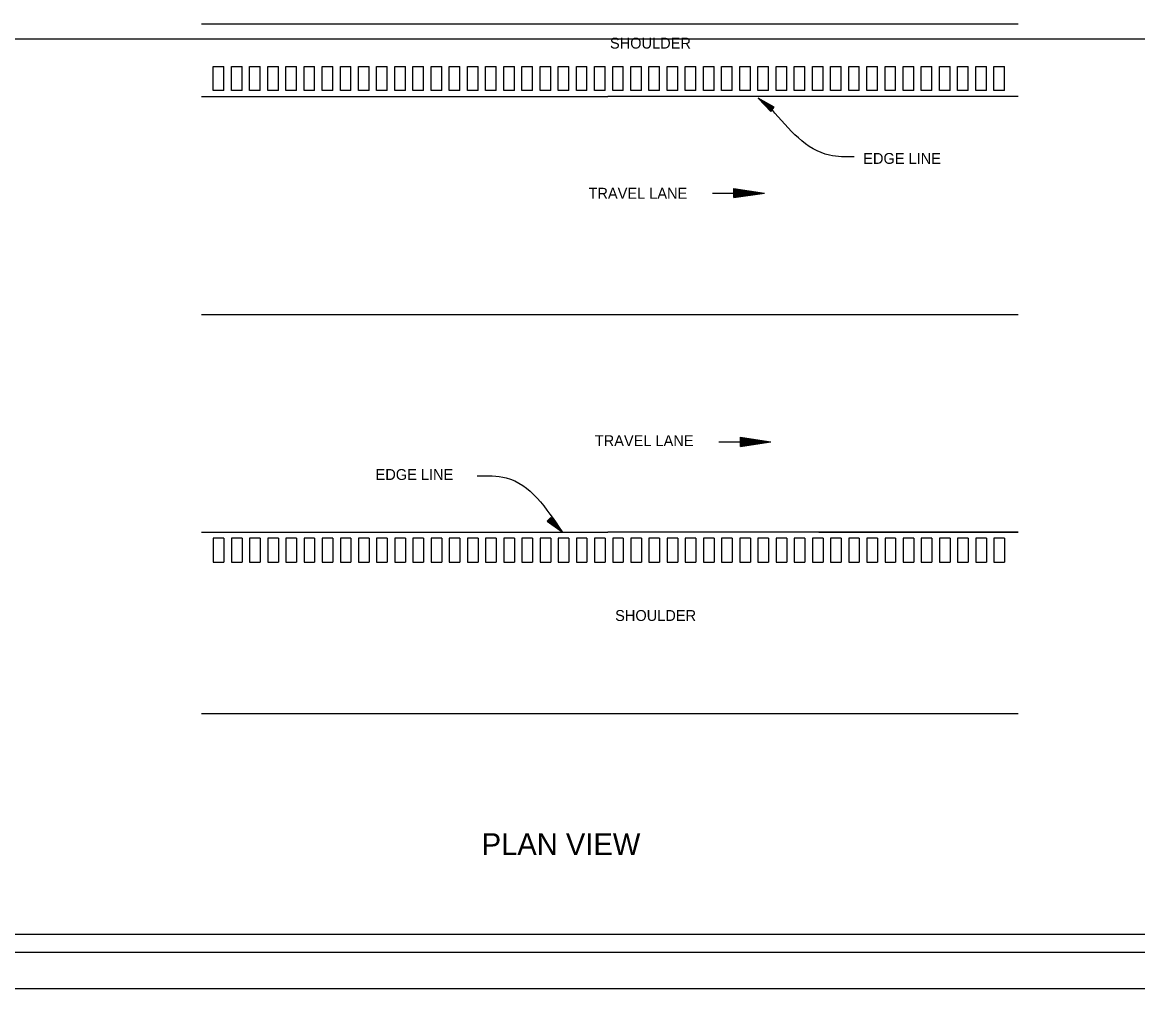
# Model space of a CAD drawing. Extents: x 1372039 to 1372773, y 376713 to 376926.
# Drawn here: x 1372550.8 to 1372673.7, y 376712.7 to 376819.2 of the extents above; entities that cross this region are included whole.
import ezdxf

# ---------------------------------------------------------------- set-up
doc = ezdxf.new("R2010")
doc.units = 0
for name, color, linetype in [('R_Border', 7, 'Continuous'), ('R_Draft', 7, 'Continuous'), ('R_No Plot', 7, 'Continuous')]:
    doc.layers.add(name, color=color, linetype=linetype)

msp = doc.modelspace()

# ---------------------------------------------------------------- linework, layer by layer
at = {"layer": 'R_Border'}
msp.add_line((1372768.01, 376716.65), (1372451.83, 376716.65), dxfattribs=at)
at = {"layer": 'R_Draft'}
for p, q in [((1372570.54, 376819), (1372660.51, 376819)), ((1372571.84, 376811.66), (1372571.84, 376814.32)), ((1372571.84, 376814.32), (1372573.01, 376814.32)), ((1372573.01, 376811.66), (1372573.01, 376814.32)), ((1372573.84, 376811.66), (1372573.84, 376814.32)), ((1372573.84, 376814.32), (1372575.01, 376814.32)), ((1372575.01, 376811.66), (1372575.01, 376814.32)), ((1372575.84, 376811.66), (1372575.84, 376814.32)), ((1372575.84, 376814.32), (1372577.01, 376814.32)), ((1372577.01, 376811.66), (1372577.01, 376814.32)), ((1372577.84, 376811.66), (1372577.84, 376814.32)), ((1372577.84, 376814.32), (1372579.01, 376814.32)), ((1372579.01, 376811.66), (1372579.01, 376814.32)), ((1372579.84, 376811.66), (1372579.84, 376814.32)), ((1372579.84, 376814.32), (1372581.01, 376814.32)), ((1372581.01, 376811.66), (1372581.01, 376814.32)), ((1372581.84, 376811.66), (1372581.84, 376814.32)), ((1372581.84, 376814.32), (1372583.01, 376814.32)), ((1372583.01, 376811.66), (1372583.01, 376814.32)), ((1372583.84, 376811.66), (1372583.84, 376814.32)), ((1372583.84, 376814.32), (1372585.01, 376814.32)), ((1372585.01, 376811.66), (1372585.01, 376814.32)), ((1372585.84, 376811.66), (1372585.84, 376814.32)), ((1372585.84, 376814.32), (1372587.01, 376814.32)), ((1372587.01, 376811.66), (1372587.01, 376814.32)), ((1372587.84, 376811.66), (1372587.84, 376814.32)), ((1372587.84, 376814.32), (1372589.01, 376814.32)), ((1372589.01, 376811.66), (1372589.01, 376814.32)), ((1372589.84, 376811.66), (1372589.84, 376814.32)), ((1372589.84, 376814.32), (1372591.01, 376814.32)), ((1372591.01, 376811.66), (1372591.01, 376814.32)), ((1372591.84, 376811.66), (1372591.84, 376814.32)), ((1372591.84, 376814.32), (1372593.01, 376814.32)), ((1372593.01, 376811.66), (1372593.01, 376814.32)), ((1372593.84, 376811.66), (1372593.84, 376814.32)), ((1372593.84, 376814.32), (1372595.01, 376814.32)), ((1372595.01, 376811.66), (1372595.01, 376814.32)), ((1372595.84, 376811.66), (1372595.84, 376814.32)), ((1372595.84, 376814.32), (1372597.01, 376814.32)), ((1372597.01, 376811.66), (1372597.01, 376814.32)), ((1372597.84, 376811.66), (1372597.84, 376814.32)), ((1372597.84, 376814.32), (1372599.01, 376814.32)), ((1372599.01, 376811.66), (1372599.01, 376814.32)), ((1372599.84, 376811.66), (1372599.84, 376814.32)), ((1372599.84, 376814.32), (1372601.01, 376814.32)), ((1372601.01, 376811.66), (1372601.01, 376814.32)), ((1372601.84, 376811.66), (1372601.84, 376814.32)), ((1372601.84, 376811.66), (1372601.84, 376814.32)), ((1372601.84, 376814.32), (1372603.01, 376814.32)), ((1372603.01, 376811.66), (1372603.01, 376814.32)), ((1372603.84, 376811.66), (1372603.84, 376814.32)), ((1372603.84, 376814.32), (1372605.01, 376814.32)), ((1372605.01, 376811.66), (1372605.01, 376814.32)), ((1372605.84, 376811.66), (1372605.84, 376814.32)), ((1372605.84, 376814.32), (1372607.01, 376814.32)), ((1372607.01, 376811.66), (1372607.01, 376814.32)), ((1372607.84, 376811.66), (1372607.84, 376814.32)), ((1372607.84, 376814.32), (1372609.01, 376814.32)), ((1372609.01, 376811.66), (1372609.01, 376814.32)), ((1372609.84, 376811.66), (1372609.84, 376814.32)), ((1372609.84, 376814.32), (1372611.01, 376814.32)), ((1372611.01, 376811.66), (1372611.01, 376814.32)), ((1372611.84, 376811.66), (1372611.84, 376814.32)), ((1372611.84, 376814.32), (1372613.01, 376814.32)), ((1372613.01, 376811.66), (1372613.01, 376814.32)), ((1372613.84, 376811.66), (1372613.84, 376814.32)), ((1372613.84, 376814.32), (1372615.01, 376814.32)), ((1372615.01, 376811.66), (1372615.01, 376814.32)), ((1372615.84, 376811.66), (1372615.84, 376814.32)), ((1372615.84, 376814.32), (1372617.01, 376814.32)), ((1372617.01, 376811.66), (1372617.01, 376814.32)), ((1372617.84, 376811.66), (1372617.84, 376814.32)), ((1372617.84, 376814.32), (1372619.01, 376814.32)), ((1372619.01, 376811.66), (1372619.01, 376814.32)), ((1372619.84, 376811.66), (1372619.84, 376814.32)), ((1372619.84, 376814.32), (1372621.01, 376814.32)), ((1372621.01, 376811.66), (1372621.01, 376814.32)), ((1372621.84, 376811.66), (1372621.84, 376814.32)), ((1372621.84, 376814.32), (1372623.01, 376814.32)), ((1372623.01, 376811.66), (1372623.01, 376814.32)), ((1372623.84, 376811.66), (1372623.84, 376814.32)), ((1372623.84, 376814.32), (1372625.01, 376814.32)), ((1372625.01, 376811.66), (1372625.01, 376814.32)), ((1372625.84, 376811.66), (1372625.84, 376814.32)), ((1372625.84, 376814.32), (1372627.01, 376814.32)), ((1372627.01, 376811.66), (1372627.01, 376814.32)), ((1372627.84, 376811.66), (1372627.84, 376814.32)), ((1372627.84, 376814.32), (1372629.01, 376814.32)), ((1372629.01, 376811.66), (1372629.01, 376814.32)), ((1372629.84, 376811.66), (1372629.84, 376814.32)), ((1372629.84, 376814.32), (1372631.01, 376814.32)), ((1372631.01, 376811.66), (1372631.01, 376814.32)), ((1372631.84, 376811.66), (1372631.84, 376814.32)), ((1372631.84, 376814.32), (1372633.01, 376814.32)), ((1372633.01, 376811.66), (1372633.01, 376814.32)), ((1372633.84, 376811.66), (1372633.84, 376814.32)), ((1372633.84, 376814.32), (1372635.01, 376814.32)), ((1372635.01, 376811.66), (1372635.01, 376814.32)), ((1372635.84, 376811.66), (1372635.84, 376814.32)), ((1372635.84, 376814.32), (1372637.01, 376814.32)), ((1372637.01, 376811.66), (1372637.01, 376814.32)), ((1372637.84, 376811.66), (1372637.84, 376814.32)), ((1372637.84, 376814.32), (1372639.01, 376814.32)), ((1372639.01, 376811.66), (1372639.01, 376814.32)), ((1372639.84, 376811.66), (1372639.84, 376814.32)), ((1372639.84, 376814.32), (1372641.01, 376814.32)), ((1372641.01, 376811.66), (1372641.01, 376814.32)), ((1372641.84, 376811.66), (1372641.84, 376814.32)), ((1372641.84, 376814.32), (1372643.01, 376814.32)), ((1372643.01, 376811.66), (1372643.01, 376814.32)), ((1372643.84, 376811.66), (1372643.84, 376814.32)), ((1372643.84, 376814.32), (1372645.01, 376814.32)), ((1372645.01, 376811.66), (1372645.01, 376814.32)), ((1372645.84, 376811.66), (1372645.84, 376814.32)), ((1372645.84, 376814.32), (1372647.01, 376814.32)), ((1372647.01, 376811.66), (1372647.01, 376814.32)), ((1372647.84, 376811.66), (1372647.84, 376814.32)), ((1372647.84, 376814.32), (1372649.01, 376814.32)), ((1372649.01, 376811.66), (1372649.01, 376814.32)), ((1372649.84, 376811.66), (1372649.84, 376814.32)), ((1372649.84, 376814.32), (1372651.01, 376814.32)), ((1372651.01, 376811.66), (1372651.01, 376814.32)), ((1372651.84, 376811.66), (1372651.84, 376814.32)), ((1372651.84, 376814.32), (1372653.01, 376814.32)), ((1372653.01, 376811.66), (1372653.01, 376814.32)), ((1372653.84, 376811.66), (1372653.84, 376814.32)), ((1372653.84, 376814.32), (1372655.01, 376814.32)), ((1372655.01, 376811.66), (1372655.01, 376814.32)), ((1372655.84, 376811.66), (1372655.84, 376814.32)), ((1372655.84, 376814.32), (1372657.01, 376814.32)), ((1372657.01, 376811.66), (1372657.01, 376814.32)), ((1372657.84, 376811.66), (1372657.84, 376814.32)), ((1372657.84, 376814.32), (1372659.01, 376814.32)), ((1372659.01, 376811.66), (1372659.01, 376814.32)), ((1372570.54, 376811), (1372615.32, 376811)), ((1372573.01, 376811.66), (1372571.84, 376811.66)), ((1372575.01, 376811.66), (1372573.84, 376811.66)), ((1372577.01, 376811.66), (1372575.84, 376811.66)), ((1372579.01, 376811.66), (1372577.84, 376811.66)), ((1372581.01, 376811.66), (1372579.84, 376811.66)), ((1372583.01, 376811.66), (1372581.84, 376811.66)), ((1372585.01, 376811.66), (1372583.84, 376811.66)), ((1372587.01, 376811.66), (1372585.84, 376811.66)), ((1372589.01, 376811.66), (1372587.84, 376811.66)), ((1372591.01, 376811.66), (1372589.84, 376811.66)), ((1372593.01, 376811.66), (1372591.84, 376811.66)), ((1372595.01, 376811.66), (1372593.84, 376811.66)), ((1372597.01, 376811.66), (1372595.84, 376811.66)), ((1372599.01, 376811.66), (1372597.84, 376811.66)), ((1372601.01, 376811.66), (1372599.84, 376811.66)), ((1372603.01, 376811.66), (1372601.84, 376811.66)), ((1372605.01, 376811.66), (1372603.84, 376811.66)), ((1372607.01, 376811.66), (1372605.84, 376811.66)), ((1372609.01, 376811.66), (1372607.84, 376811.66)), ((1372611.01, 376811.66), (1372609.84, 376811.66)), ((1372613.01, 376811.66), (1372611.84, 376811.66)), ((1372615.01, 376811.66), (1372613.84, 376811.66)), ((1372660.51, 376811), (1372615.32, 376811)), ((1372617.01, 376811.66), (1372615.84, 376811.66)), ((1372619.01, 376811.66), (1372617.84, 376811.66)), ((1372621.01, 376811.66), (1372619.84, 376811.66)), ((1372623.01, 376811.66), (1372621.84, 376811.66)), ((1372625.01, 376811.66), (1372623.84, 376811.66)), ((1372627.01, 376811.66), (1372625.84, 376811.66)), ((1372629.01, 376811.66), (1372627.84, 376811.66)), ((1372631.01, 376811.66), (1372629.84, 376811.66)), ((1372633.01, 376811.66), (1372631.84, 376811.66)), ((1372635.01, 376811.66), (1372633.84, 376811.66)), ((1372637.01, 376811.66), (1372635.84, 376811.66)), ((1372639.01, 376811.66), (1372637.84, 376811.66)), ((1372641.01, 376811.66), (1372639.84, 376811.66)), ((1372643.01, 376811.66), (1372641.84, 376811.66)), ((1372645.01, 376811.66), (1372643.84, 376811.66)), ((1372647.01, 376811.66), (1372645.84, 376811.66)), ((1372649.01, 376811.66), (1372647.84, 376811.66)), ((1372651.01, 376811.66), (1372649.84, 376811.66)), ((1372653.01, 376811.66), (1372651.84, 376811.66)), ((1372655.01, 376811.66), (1372653.84, 376811.66)), ((1372657.01, 376811.66), (1372655.84, 376811.66)), ((1372659.01, 376811.66), (1372657.84, 376811.66)), ((1372633.25, 376809.36), (1372631.87, 376810.84)), ((1372633.62, 376809.83), (1372631.87, 376810.84)), ((1372633.28, 376809.4), (1372632.13, 376810.63)), ((1372633.59, 376809.79), (1372632.13, 376810.63)), ((1372633.56, 376809.75), (1372632.4, 376810.42)), ((1372633.31, 376809.44), (1372632.4, 376810.42)), ((1372633.34, 376809.48), (1372632.66, 376810.21)), ((1372633.53, 376809.71), (1372632.66, 376810.21)), ((1372633.49, 376809.67), (1372632.93, 376810)), ((1372633.37, 376809.52), (1372632.93, 376810)), ((1372633.46, 376809.63), (1372633.19, 376809.79)), ((1372633.4, 376809.56), (1372633.19, 376809.79)), ((1372633.25, 376809.36), (1372633.62, 376809.83)), ((1372626.83, 376800.37), (1372632.55, 376800.37)), ((1372629.19, 376800.87), (1372632.55, 376800.37)), ((1372629.19, 376799.86), (1372629.19, 376800.87)), ((1372629.19, 376800.79), (1372631.99, 376800.37)), ((1372629.19, 376800.7), (1372631.42, 376800.37)), ((1372629.19, 376800.62), (1372630.86, 376800.37)), ((1372629.19, 376800.53), (1372630.29, 376800.37)), ((1372629.19, 376800.45), (1372629.73, 376800.37)), ((1372629.19, 376799.86), (1372632.55, 376800.37)), ((1372629.19, 376800.21), (1372630.29, 376800.37)), ((1372629.19, 376800.03), (1372631.42, 376800.37)), ((1372629.19, 376799.95), (1372631.99, 376800.37)), ((1372629.19, 376800.12), (1372630.86, 376800.37)), ((1372629.19, 376800.28), (1372629.73, 376800.37)), ((1372570.54, 376786.99), (1372660.51, 376786.99)), ((1372627.55, 376772.95), (1372633.27, 376772.95)), ((1372629.91, 376773.44), (1372633.27, 376772.95)), ((1372629.91, 376772.44), (1372629.91, 376773.44)), ((1372629.91, 376773.36), (1372632.71, 376772.95)), ((1372629.91, 376773.28), (1372632.14, 376772.95)), ((1372629.91, 376773.19), (1372631.58, 376772.95)), ((1372629.91, 376773.11), (1372631.01, 376772.95)), ((1372629.91, 376773.03), (1372630.45, 376772.95)), ((1372629.91, 376772.44), (1372633.27, 376772.95)), ((1372629.91, 376772.78), (1372631.01, 376772.95)), ((1372629.91, 376772.61), (1372632.14, 376772.95)), ((1372629.91, 376772.52), (1372632.71, 376772.95)), ((1372629.91, 376772.69), (1372631.58, 376772.95)), ((1372629.91, 376772.86), (1372630.45, 376772.95)), ((1372609.04, 376764.62), (1372608.62, 376764.19)), ((1372608.69, 376764.26), (1372609.78, 376763.48)), ((1372608.73, 376764.29), (1372609.54, 376763.71)), ((1372608.76, 376764.33), (1372609.3, 376763.95)), ((1372608.8, 376764.37), (1372609.06, 376764.18)), ((1372608.86, 376764.43), (1372609.06, 376764.18)), ((1372608.9, 376764.47), (1372609.3, 376763.95)), ((1372608.93, 376764.51), (1372609.54, 376763.71)), ((1372608.97, 376764.54), (1372609.78, 376763.48)), ((1372609, 376764.58), (1372610.03, 376763.24)), ((1372609.04, 376764.62), (1372610.27, 376763.01)), ((1372608.62, 376764.19), (1372610.27, 376763.01)), ((1372608.66, 376764.22), (1372610.03, 376763.24)), ((1372570.54, 376762.99), (1372615.32, 376762.99)), ((1372573.01, 376762.33), (1372571.84, 376762.33)), ((1372571.84, 376762.33), (1372571.84, 376759.67)), ((1372573.01, 376762.33), (1372573.01, 376759.67)), ((1372575.01, 376762.33), (1372573.84, 376762.33)), ((1372573.84, 376762.33), (1372573.84, 376759.67)), ((1372575.01, 376762.33), (1372575.01, 376759.67)), ((1372577.01, 376762.33), (1372575.84, 376762.33)), ((1372575.84, 376762.33), (1372575.84, 376759.67)), ((1372577.01, 376762.33), (1372577.01, 376759.67)), ((1372579.01, 376762.33), (1372577.84, 376762.33)), ((1372577.84, 376762.33), (1372577.84, 376759.67)), ((1372579.01, 376762.33), (1372579.01, 376759.67)), ((1372581.01, 376762.33), (1372579.84, 376762.33)), ((1372579.84, 376762.33), (1372579.84, 376759.67)), ((1372581.01, 376762.33), (1372581.01, 376759.67)), ((1372583.01, 376762.33), (1372581.84, 376762.33)), ((1372581.84, 376762.33), (1372581.84, 376759.67)), ((1372583.01, 376762.33), (1372583.01, 376759.67)), ((1372585.01, 376762.33), (1372583.84, 376762.33)), ((1372583.84, 376762.33), (1372583.84, 376759.67)), ((1372585.01, 376762.33), (1372585.01, 376759.67)), ((1372587.01, 376762.33), (1372585.84, 376762.33)), ((1372585.84, 376762.33), (1372585.84, 376759.67)), ((1372587.01, 376762.33), (1372587.01, 376759.67)), ((1372589.01, 376762.33), (1372587.84, 376762.33)), ((1372587.84, 376762.33), (1372587.84, 376759.67)), ((1372589.01, 376762.33), (1372589.01, 376759.67)), ((1372591.01, 376762.33), (1372589.84, 376762.33)), ((1372589.84, 376762.33), (1372589.84, 376759.67)), ((1372591.01, 376762.33), (1372591.01, 376759.67)), ((1372593.01, 376762.33), (1372591.84, 376762.33)), ((1372591.84, 376762.33), (1372591.84, 376759.67)), ((1372593.01, 376762.33), (1372593.01, 376759.67)), ((1372595.01, 376762.33), (1372593.84, 376762.33)), ((1372593.84, 376762.33), (1372593.84, 376759.67)), ((1372595.01, 376762.33), (1372595.01, 376759.67)), ((1372597.01, 376762.33), (1372595.84, 376762.33)), ((1372595.84, 376762.33), (1372595.84, 376759.67)), ((1372597.01, 376762.33), (1372597.01, 376759.67)), ((1372599.01, 376762.33), (1372597.84, 376762.33)), ((1372597.84, 376762.33), (1372597.84, 376759.67)), ((1372599.01, 376762.33), (1372599.01, 376759.67)), ((1372601.01, 376762.33), (1372599.84, 376762.33)), ((1372599.84, 376762.33), (1372599.84, 376759.67)), ((1372601.01, 376762.33), (1372601.01, 376759.67)), ((1372603.01, 376762.33), (1372601.84, 376762.33)), ((1372601.84, 376762.33), (1372601.84, 376759.67)), ((1372603.01, 376762.33), (1372603.01, 376759.67)), ((1372605.01, 376762.33), (1372603.84, 376762.33)), ((1372603.84, 376762.33), (1372603.84, 376759.67)), ((1372605.01, 376762.33), (1372605.01, 376759.67)), ((1372607.01, 376762.33), (1372605.84, 376762.33)), ((1372605.84, 376762.33), (1372605.84, 376759.67)), ((1372607.01, 376762.33), (1372607.01, 376759.67)), ((1372609.01, 376762.33), (1372607.84, 376762.33)), ((1372607.84, 376762.33), (1372607.84, 376759.67)), ((1372609.01, 376762.33), (1372609.01, 376759.67)), ((1372611.01, 376762.33), (1372609.84, 376762.33)), ((1372609.84, 376762.33), (1372609.84, 376759.67)), ((1372611.01, 376762.33), (1372611.01, 376759.67)), ((1372613.01, 376762.33), (1372611.84, 376762.33)), ((1372611.84, 376762.33), (1372611.84, 376759.67)), ((1372613.01, 376762.33), (1372613.01, 376759.67)), ((1372615.01, 376762.33), (1372613.84, 376762.33)), ((1372613.84, 376762.33), (1372613.84, 376759.67)), ((1372615.01, 376762.33), (1372615.01, 376759.67)), ((1372660.51, 376762.99), (1372615.32, 376762.99)), ((1372617.01, 376762.33), (1372615.84, 376762.33)), ((1372615.84, 376762.33), (1372615.84, 376759.67)), ((1372617.01, 376762.33), (1372617.01, 376759.67)), ((1372619.01, 376762.33), (1372617.84, 376762.33)), ((1372617.84, 376762.33), (1372617.84, 376759.67)), ((1372619.01, 376762.33), (1372619.01, 376759.67)), ((1372621.01, 376762.33), (1372619.84, 376762.33)), ((1372619.84, 376762.33), (1372619.84, 376759.67)), ((1372621.01, 376762.33), (1372621.01, 376759.67)), ((1372623.01, 376762.33), (1372621.84, 376762.33)), ((1372621.84, 376762.33), (1372621.84, 376759.67)), ((1372623.01, 376762.33), (1372623.01, 376759.67)), ((1372625.01, 376762.33), (1372623.84, 376762.33)), ((1372623.84, 376762.33), (1372623.84, 376759.67)), ((1372625.01, 376762.33), (1372625.01, 376759.67)), ((1372627.01, 376762.33), (1372625.84, 376762.33)), ((1372625.84, 376762.33), (1372625.84, 376759.67)), ((1372627.01, 376762.33), (1372627.01, 376759.67)), ((1372629.01, 376762.33), (1372627.84, 376762.33)), ((1372627.84, 376762.33), (1372627.84, 376759.67)), ((1372629.01, 376762.33), (1372629.01, 376759.67)), ((1372631.01, 376762.33), (1372629.84, 376762.33)), ((1372629.84, 376762.33), (1372629.84, 376759.67)), ((1372631.01, 376762.33), (1372631.01, 376759.67)), ((1372633.01, 376762.33), (1372631.84, 376762.33)), ((1372631.84, 376762.33), (1372631.84, 376759.67)), ((1372633.01, 376762.33), (1372633.01, 376759.67)), ((1372635.01, 376762.33), (1372633.84, 376762.33)), ((1372633.84, 376762.33), (1372633.84, 376759.67)), ((1372635.01, 376762.33), (1372635.01, 376759.67)), ((1372637.01, 376762.33), (1372635.84, 376762.33)), ((1372635.84, 376762.33), (1372635.84, 376759.67)), ((1372637.01, 376762.33), (1372637.01, 376759.67)), ((1372639.01, 376762.33), (1372637.84, 376762.33)), ((1372637.84, 376762.33), (1372637.84, 376759.67)), ((1372638.54, 376762.99), (1372660.51, 376762.99)), ((1372639.01, 376762.33), (1372639.01, 376759.67)), ((1372641.01, 376762.33), (1372639.84, 376762.33)), ((1372639.84, 376762.33), (1372639.84, 376759.67)), ((1372641.01, 376762.33), (1372641.01, 376759.67)), ((1372643.01, 376762.33), (1372641.84, 376762.33)), ((1372641.84, 376762.33), (1372641.84, 376759.67)), ((1372643.01, 376762.33), (1372643.01, 376759.67)), ((1372645.01, 376762.33), (1372643.84, 376762.33)), ((1372643.84, 376762.33), (1372643.84, 376759.67)), ((1372645.01, 376762.33), (1372645.01, 376759.67)), ((1372647.01, 376762.33), (1372645.84, 376762.33)), ((1372645.84, 376762.33), (1372645.84, 376759.67)), ((1372647.01, 376762.33), (1372647.01, 376759.67)), ((1372649.01, 376762.33), (1372647.84, 376762.33)), ((1372647.84, 376762.33), (1372647.84, 376759.67)), ((1372649.01, 376762.33), (1372649.01, 376759.67)), ((1372651.01, 376762.33), (1372649.84, 376762.33)), ((1372649.84, 376762.33), (1372649.84, 376759.67)), ((1372651.01, 376762.33), (1372651.01, 376759.67)), ((1372653.01, 376762.33), (1372651.84, 376762.33)), ((1372651.84, 376762.33), (1372651.84, 376759.67)), ((1372653.01, 376762.33), (1372653.01, 376759.67)), ((1372655.01, 376762.33), (1372653.84, 376762.33)), ((1372653.84, 376762.33), (1372653.84, 376759.67)), ((1372655.01, 376762.33), (1372655.01, 376759.67)), ((1372657.01, 376762.33), (1372655.84, 376762.33)), ((1372655.84, 376762.33), (1372655.84, 376759.67)), ((1372657.01, 376762.33), (1372657.01, 376759.67)), ((1372659.01, 376762.33), (1372657.84, 376762.33)), ((1372657.84, 376762.33), (1372657.84, 376759.67)), ((1372659.01, 376762.33), (1372659.01, 376759.67)), ((1372571.84, 376759.67), (1372573.01, 376759.67)), ((1372573.84, 376759.67), (1372575.01, 376759.67)), ((1372575.84, 376759.67), (1372577.01, 376759.67)), ((1372577.84, 376759.67), (1372579.01, 376759.67)), ((1372579.84, 376759.67), (1372581.01, 376759.67)), ((1372581.84, 376759.67), (1372583.01, 376759.67)), ((1372583.84, 376759.67), (1372585.01, 376759.67)), ((1372585.84, 376759.67), (1372587.01, 376759.67)), ((1372587.84, 376759.67), (1372589.01, 376759.67)), ((1372589.84, 376759.67), (1372591.01, 376759.67)), ((1372591.84, 376759.67), (1372593.01, 376759.67)), ((1372593.84, 376759.67), (1372595.01, 376759.67)), ((1372595.84, 376759.67), (1372597.01, 376759.67)), ((1372597.84, 376759.67), (1372599.01, 376759.67)), ((1372599.84, 376759.67), (1372601.01, 376759.67)), ((1372601.84, 376759.67), (1372603.01, 376759.67)), ((1372603.84, 376759.67), (1372605.01, 376759.67)), ((1372605.84, 376759.67), (1372607.01, 376759.67)), ((1372607.84, 376759.67), (1372609.01, 376759.67)), ((1372609.84, 376759.67), (1372611.01, 376759.67)), ((1372611.84, 376759.67), (1372613.01, 376759.67)), ((1372613.84, 376759.67), (1372615.01, 376759.67)), ((1372615.84, 376759.67), (1372617.01, 376759.67)), ((1372617.84, 376759.67), (1372619.01, 376759.67)), ((1372619.84, 376759.67), (1372621.01, 376759.67)), ((1372621.84, 376759.67), (1372623.01, 376759.67)), ((1372623.84, 376759.67), (1372625.01, 376759.67)), ((1372625.84, 376759.67), (1372627.01, 376759.67)), ((1372627.84, 376759.67), (1372629.01, 376759.67)), ((1372629.84, 376759.67), (1372631.01, 376759.67)), ((1372631.84, 376759.67), (1372633.01, 376759.67)), ((1372633.84, 376759.67), (1372635.01, 376759.67)), ((1372635.84, 376759.67), (1372637.01, 376759.67)), ((1372637.84, 376759.67), (1372639.01, 376759.67)), ((1372639.84, 376759.67), (1372641.01, 376759.67)), ((1372641.84, 376759.67), (1372643.01, 376759.67)), ((1372643.84, 376759.67), (1372645.01, 376759.67)), ((1372645.84, 376759.67), (1372647.01, 376759.67)), ((1372647.84, 376759.67), (1372649.01, 376759.67)), ((1372649.84, 376759.67), (1372651.01, 376759.67)), ((1372651.84, 376759.67), (1372653.01, 376759.67)), ((1372653.84, 376759.67), (1372655.01, 376759.67)), ((1372655.84, 376759.67), (1372657.01, 376759.67)), ((1372657.84, 376759.67), (1372659.01, 376759.67)), ((1372570.54, 376742.99), (1372660.51, 376742.99))]:
    msp.add_line(p, q, dxfattribs=at)
for points in [[(1372642.44, 376804.34), (1372639.73, 376804.53), (1372633.36, 376809.61)], [(1372600.92, 376769.2), (1372604.1, 376768.98), (1372610.27, 376763.01)]]:
    msp.add_spline(points, degree=3, dxfattribs=at)
at = {"layer": 'R_No Plot'}
msp.add_line((1372439.43, 376712.67), (1372772.76, 376712.67), dxfattribs=at)
for points in [[(1372439.42, 376926), (1372772.76, 376926), (1372772.76, 376712.66), (1372439.42, 376712.66)], [(1372453.83, 376920.11), (1372703.37, 376920.11), (1372703.37, 376910.23), (1372720.91, 376910.23), (1372745.01, 376910.23), (1372745.01, 376887.89), (1372766.01, 376887.89), (1372766.01, 376718.65), (1372453.83, 376718.65)], [(1372453.83, 376817.38), (1372766.01, 376817.38), (1372766.01, 376718.65), (1372453.83, 376718.65)]]:
    msp.add_lwpolyline(points, close=True, dxfattribs=at)

# ---------------------------------------------------------------- texts
at = {"layer": 'R_Draft'}
for s, height, p in [('SHOULDER', 1.2, (1372615.54, 376816.29)), ('EDGE LINE', 1.2, (1372643.44, 376803.58)), ('TRAVEL LANE', 1.2, (1372613.18, 376799.74)), ('TRAVEL LANE', 1.2, (1372613.87, 376772.47)), ('EDGE LINE', 1.2, (1372589.72, 376768.74)), ('SHOULDER', 1.2, (1372616.11, 376753.2)), ('PLAN VIEW ', 2.4, (1372601.41, 376727.4))]:
    msp.add_text(s, height=height, dxfattribs=at).set_placement(p)

doc.saveas('drawing.dxf')
